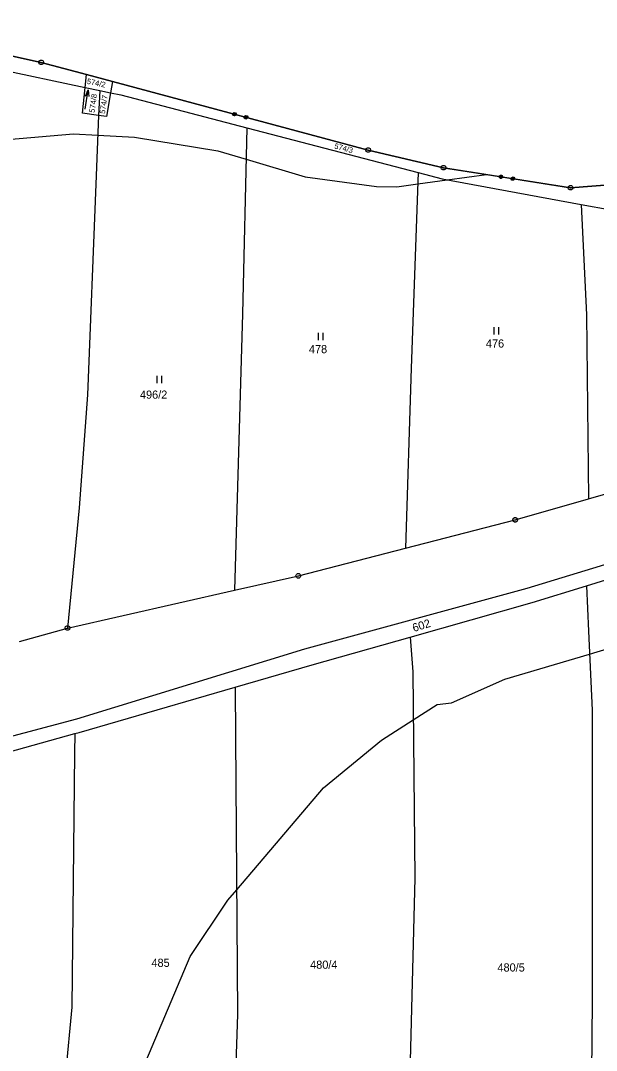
# Model space of a CAD drawing. Extents: x -760978 to -760029, y -1177282 to -1176414.
# Drawn here: x -760280.9 to -760161.1, y -1176642.6 to -1176428.3 of the extents above; entities that cross this region are included whole.
import ezdxf

# ---------------------------------------------------------------- set-up
doc = ezdxf.new("R2010")
doc.units = 0
for name, color, linetype in [('1', 7, 'Continuous'), ('11', 7, 'Continuous'), ('2', 7, 'Continuous'), ('3', 7, 'Continuous'), ('8', 7, 'Continuous')]:
    doc.layers.add(name, color=color, linetype=linetype)

msp = doc.modelspace()

# ---------------------------------------------------------------- linework, layer by layer
at = {"layer": '1'}
for p, q in [((-760276.6, -1176437.03), (-760316.13, -1176428.34)), ((-760296.58, -1176436.11), (-760267.45, -1176442.25)), ((-760267.18, -1176439.56), (-760276.6, -1176437.03)), ((-760267.45, -1176442.25), (-760267.18, -1176439.56)), ((-760261.76, -1176441.01), (-760267.18, -1176439.56)), ((-760261.76, -1176441.01), (-760262.18, -1176443.36)), ((-760208.55, -1176455.27), (-760261.76, -1176441.01)), ((-760267.99, -1176447.61), (-760267.45, -1176442.25)), ((-760267.45, -1176442.25), (-760264.44, -1176442.88)), ((-760264.44, -1176442.88), (-760264.66, -1176448.07)), ((-760264.44, -1176442.88), (-760262.18, -1176443.36)), ((-760262.18, -1176443.36), (-760263.05, -1176448.29)), ((-760262.18, -1176443.36), (-760260.03, -1176443.81)), ((-760260.03, -1176443.81), (-760233.79, -1176450.66)), ((-760264.66, -1176448.07), (-760267.99, -1176447.61)), ((-760264.66, -1176448.07), (-760265.25, -1176462.4)), ((-760263.05, -1176448.29), (-760264.66, -1176448.07)), ((-760233.79, -1176450.66), (-760234.75, -1176489.37)), ((-760233.79, -1176450.66), (-760198.18, -1176459.96)), ((-760192.88, -1176458.96), (-760208.55, -1176455.27)), ((-760198.18, -1176459.96), (-760199.63, -1176500.65)), ((-760198.18, -1176459.96), (-760193.14, -1176461.28)), ((-760166.44, -1176463.13), (-760192.88, -1176458.96)), ((-760265.25, -1176462.4), (-760266.96, -1176506.18)), ((-760193.14, -1176461.28), (-760164.28, -1176466.59)), ((-760157.62, -1176462.47), (-760166.44, -1176463.13)), ((-760164.28, -1176466.59), (-760163.15, -1176489.6)), ((-760164.28, -1176466.59), (-760158.05, -1176467.74)), ((-760234.75, -1176489.37), (-760236.35, -1176546.88)), ((-760163.15, -1176489.6), (-760162.74, -1176527.85)), ((-760199.63, -1176500.65), (-760200.78, -1176538.13)), ((-760266.96, -1176506.18), (-760268.68, -1176529.73)), ((-760162.74, -1176527.85), (-760149.74, -1176524.1)), ((-760177.97, -1176532.25), (-760162.74, -1176527.85)), ((-760268.68, -1176529.73), (-760271.14, -1176554.74)), ((-760125.87, -1176531.35), (-760175.55, -1176546.51)), ((-760200.78, -1176538.13), (-760177.97, -1176532.25)), ((-760223.1, -1176543.89), (-760200.78, -1176538.13)), ((-760163.15, -1176545.96), (-760149.68, -1176541.8)), ((-760236.35, -1176546.88), (-760223.1, -1176543.89)), ((-760174.45, -1176549.45), (-760163.15, -1176545.96)), ((-760163.15, -1176545.96), (-760162.73, -1176555.41)), ((-760271.14, -1176554.74), (-760236.35, -1176546.88)), ((-760175.55, -1176546.51), (-760221.79, -1176559.17)), ((-760199.81, -1176556.62), (-760174.45, -1176549.45)), ((-760281.11, -1176557.51), (-760271.14, -1176554.74)), ((-760220.2, -1176562.38), (-760199.81, -1176556.62)), ((-760199.81, -1176556.62), (-760199.29, -1176563.86)), ((-760162.73, -1176555.41), (-760161.99, -1176571.84)), ((-760221.79, -1176559.17), (-760269.28, -1176573.68)), ((-760236.24, -1176567.03), (-760220.2, -1176562.38)), ((-760199.29, -1176563.86), (-760198.83, -1176606.8)), ((-760268.74, -1176576.46), (-760236.24, -1176567.03)), ((-760236.24, -1176567.03), (-760236.16, -1176577.36)), ((-760161.99, -1176571.84), (-760161.99, -1176632.33)), ((-760269.28, -1176573.68), (-760302.72, -1176582.55)), ((-760285.28, -1176581.08), (-760269.62, -1176576.7)), ((-760269.62, -1176576.7), (-760269.67, -1176580.75)), ((-760269.62, -1176576.7), (-760268.74, -1176576.46)), ((-760236.16, -1176577.36), (-760235.73, -1176635.17)), ((-760269.67, -1176580.75), (-760270.26, -1176633.65)), ((-760198.83, -1176606.8), (-760200.41, -1176667.45)), ((-760270.26, -1176633.65), (-760272.99, -1176662.87)), ((-760161.99, -1176632.33), (-760162.36, -1176686.44)), ((-760235.73, -1176635.17), (-760237.83, -1176693.67))]:
    msp.add_line(p, q, dxfattribs=at)
for points in [[(-760236.62, -1176448.08), (-760236.75, -1176447.85), (-760236.68, -1176447.59), (-760236.45, -1176447.45), (-760236.19, -1176447.52), (-760236.06, -1176447.75), (-760236.13, -1176448.01), (-760236.36, -1176448.15), (-760236.62, -1176448.08), (-760236.58, -1176448.05), (-760236.35, -1176448.11), (-760236.25, -1176448.05), (-760236.64, -1176447.95), (-760236.69, -1176447.85), (-760236.15, -1176448), (-760236.13, -1176447.92), (-760236.67, -1176447.78), (-760236.65, -1176447.7), (-760236.11, -1176447.84), (-760236.09, -1176447.77), (-760236.63, -1176447.62), (-760236.53, -1176447.56), (-760236.15, -1176447.67), (-760236.2, -1176447.57), (-760236.43, -1176447.51)], [(-760234.2, -1176448.73), (-760234.34, -1176448.49), (-760234.27, -1176448.23), (-760234.04, -1176448.1), (-760233.78, -1176448.17), (-760233.64, -1176448.4), (-760233.71, -1176448.66), (-760233.94, -1176448.8), (-760234.2, -1176448.73), (-760234.18, -1176448.69), (-760233.95, -1176448.75), (-760233.85, -1176448.7), (-760234.24, -1176448.59), (-760234.3, -1176448.49), (-760233.76, -1176448.64), (-760233.74, -1176448.56), (-760234.28, -1176448.42), (-760234.26, -1176448.34), (-760233.72, -1176448.48), (-760233.69, -1176448.41), (-760234.24, -1176448.26), (-760234.14, -1176448.21), (-760233.75, -1176448.31), (-760233.81, -1176448.21), (-760234.04, -1176448.15)], [(-760181.12, -1176461.14), (-760181.28, -1176460.92), (-760181.24, -1176460.65), (-760181.02, -1176460.5), (-760180.75, -1176460.54), (-760180.6, -1176460.76), (-760180.64, -1176461.02), (-760180.86, -1176461.18), (-760181.12, -1176461.14), (-760181.09, -1176461.1), (-760180.85, -1176461.14), (-760180.76, -1176461.07), (-760181.15, -1176461.01), (-760181.22, -1176460.92), (-760180.67, -1176461.01), (-760180.65, -1176460.93), (-760181.21, -1176460.84), (-760181.19, -1176460.76), (-760180.64, -1176460.85), (-760180.63, -1176460.77), (-760181.18, -1176460.68), (-760181.09, -1176460.62), (-760180.7, -1176460.68), (-760180.76, -1176460.59), (-760181, -1176460.55)], [(-760178.65, -1176461.53), (-760178.81, -1176461.31), (-760178.77, -1176461.04), (-760178.55, -1176460.89), (-760178.28, -1176460.93), (-760178.13, -1176461.15), (-760178.17, -1176461.41), (-760178.39, -1176461.57), (-760178.65, -1176461.53), (-760178.64, -1176461.49), (-760178.4, -1176461.53), (-760178.31, -1176461.46), (-760178.7, -1176461.4), (-760178.77, -1176461.31), (-760178.22, -1176461.39), (-760178.2, -1176461.32), (-760178.76, -1176461.23), (-760178.75, -1176461.15), (-760178.19, -1176461.24), (-760178.18, -1176461.16), (-760178.73, -1176461.07), (-760178.64, -1176461), (-760178.25, -1176461.07), (-760178.31, -1176460.97), (-760178.55, -1176460.94)]]:
    msp.add_lwpolyline(points, dxfattribs=at)
at = {"layer": '11'}
for points in [[(-760610.45, -1176430.21), (-760611.11, -1176435.21), (-760607.21, -1176435.9), (-760556.03, -1176460.82), (-760555.89, -1176460.89), (-760545.74, -1176465.83), (-760487.96, -1176478.86), (-760457.63, -1176475.7), (-760439.57, -1176472.8), (-760424.85, -1176466.78), (-760424.82, -1176466.77), (-760413.52, -1176462.15), (-760377.01, -1176441.98), (-760344.63, -1176429.59), (-760316.13, -1176428.34), (-760276.6, -1176437.03), (-760267.18, -1176439.56), (-760261.76, -1176441.01)], [(-760261.76, -1176441.01), (-760208.55, -1176455.27), (-760192.88, -1176458.96), (-760183.97, -1176460.36)], [(-760183.97, -1176460.36), (-760166.44, -1176463.13), (-760157.62, -1176462.47), (-760153.69, -1176462.18), (-760135.67, -1176460.84), (-760121.19, -1176458.87), (-760106.95, -1176454.96), (-760087.58, -1176448.84)], [(-760463.52, -1176510.97), (-760456.38, -1176508.74), (-760455.84, -1176508.57), (-760440.39, -1176497.85), (-760434.43, -1176496.69), (-760400.64, -1176484.31), (-760369.55, -1176472.91), (-760361.85, -1176469.24), (-760336.22, -1176462.2), (-760324.34, -1176458.93), (-760306.03, -1176455.04), (-760299.86, -1176454.5), (-760269.91, -1176451.9), (-760264.83, -1176452.17), (-760257.19, -1176452.57), (-760239.84, -1176455.43), (-760233.95, -1176457.19), (-760221.69, -1176460.86), (-760206.87, -1176462.83), (-760202.63, -1176462.91), (-760198.26, -1176462.31), (-760192.1, -1176461.47), (-760183.97, -1176460.36)], [(-760254.86, -1176644.92), (-760245.59, -1176623.07), (-760237.75, -1176611.35), (-760235.92, -1176609.2), (-760217.85, -1176588), (-760205.81, -1176578.07), (-760199.18, -1176573.83), (-760194.23, -1176570.66), (-760191.25, -1176570.29), (-760180.14, -1176565.41), (-760162.52, -1176560.15), (-760149.44, -1176556.25), (-760149.34, -1176556.23), (-760124.36, -1176551.99), (-760117.95, -1176550.9), (-760100.57, -1176548.71), (-760087.11, -1176547.01), (-760071.18, -1176545), (-760059.84, -1176544.57), (-760056.32, -1176544.43)]]:
    msp.add_lwpolyline(points, dxfattribs=at)
at = {"layer": '3'}
for p, q in [((-760267.45, -1176446.74), (-760266.83, -1176442.76)), ((-760182.4, -1176492.16), (-760182.4, -1176493.66)), ((-760181.4, -1176493.66), (-760181.4, -1176492.16)), ((-760218.96, -1176493.32), (-760218.96, -1176494.82)), ((-760217.96, -1176494.82), (-760217.96, -1176493.32)), ((-760252.53, -1176502.27), (-760252.53, -1176503.77)), ((-760251.53, -1176503.77), (-760251.53, -1176502.27))]:
    msp.add_line(p, q, dxfattribs=at)
msp.add_lwpolyline([(-760267.37, -1176444.04), (-760266.83, -1176442.76), (-760266.7, -1176444.14)], dxfattribs=at)
at = {"layer": '8'}
for p, q in [((-760276.72, -1176437.03), (-760276.48, -1176437.03)), ((-760208.67, -1176455.27), (-760208.43, -1176455.27)), ((-760193, -1176458.96), (-760192.76, -1176458.96)), ((-760166.56, -1176463.13), (-760166.32, -1176463.13)), ((-760178.09, -1176532.25), (-760177.85, -1176532.25)), ((-760223.22, -1176543.89), (-760222.98, -1176543.89)), ((-760271.26, -1176554.74), (-760271.02, -1176554.74))]:
    msp.add_line(p, q, dxfattribs=at)
for points in [[(-760276.45, -1176436.55), (-760276.2, -1176436.73), (-760276.1, -1176437.02), (-760276.2, -1176437.31), (-760276.45, -1176437.49), (-760276.76, -1176437.49), (-760277.01, -1176437.31), (-760277.11, -1176437.02), (-760277.01, -1176436.73), (-760276.76, -1176436.55)], [(-760208.4, -1176454.79), (-760208.15, -1176454.97), (-760208.05, -1176455.26), (-760208.15, -1176455.55), (-760208.4, -1176455.73), (-760208.71, -1176455.73), (-760208.96, -1176455.55), (-760209.06, -1176455.26), (-760208.96, -1176454.97), (-760208.71, -1176454.79)], [(-760192.73, -1176458.48), (-760192.48, -1176458.66), (-760192.38, -1176458.95), (-760192.48, -1176459.24), (-760192.73, -1176459.42), (-760193.04, -1176459.42), (-760193.29, -1176459.24), (-760193.39, -1176458.95), (-760193.29, -1176458.66), (-760193.04, -1176458.48)], [(-760166.29, -1176462.65), (-760166.04, -1176462.83), (-760165.94, -1176463.12), (-760166.04, -1176463.41), (-760166.29, -1176463.59), (-760166.6, -1176463.59), (-760166.85, -1176463.41), (-760166.95, -1176463.12), (-760166.85, -1176462.83), (-760166.6, -1176462.65)], [(-760177.82, -1176531.77), (-760177.57, -1176531.95), (-760177.47, -1176532.24), (-760177.57, -1176532.53), (-760177.82, -1176532.71), (-760178.13, -1176532.71), (-760178.38, -1176532.53), (-760178.48, -1176532.24), (-760178.38, -1176531.95), (-760178.13, -1176531.77)], [(-760222.95, -1176543.41), (-760222.7, -1176543.59), (-760222.6, -1176543.88), (-760222.7, -1176544.17), (-760222.95, -1176544.35), (-760223.26, -1176544.35), (-760223.51, -1176544.17), (-760223.61, -1176543.88), (-760223.51, -1176543.59), (-760223.26, -1176543.41)], [(-760270.99, -1176554.26), (-760270.74, -1176554.44), (-760270.64, -1176554.73), (-760270.74, -1176555.02), (-760270.99, -1176555.2), (-760271.3, -1176555.2), (-760271.55, -1176555.02), (-760271.65, -1176554.73), (-760271.55, -1176554.44), (-760271.3, -1176554.26)]]:
    msp.add_lwpolyline(points, close=True, dxfattribs=at)

# ---------------------------------------------------------------- texts
at = {"layer": '2'}
for s, height, rotation, p in [('574/2', 1.14, 347.9, (-760267.2, -1176441.47)), ('574/8', 1.14, 82.4486, (-760265.51, -1176447.58)), ('574/7', 1.14, 80.787, (-760263.37, -1176447.82)), ('574/3', 1.14, 345.0925, (-760215.7, -1176454.93)), ('602', 1.7, 17.246, (-760199.06, -1176555.57))]:
    msp.add_text(s, height=height, rotation=rotation, dxfattribs=at).set_placement(p)
for s, p in [('476', (-760184.07, -1176496.38)), ('478', (-760220.9, -1176497.55)), ('496/2', (-760256.06, -1176507.02)), ('485', (-760253.67, -1176625.25)), ('480/4', (-760220.65, -1176625.64)), ('480/5', (-760181.67, -1176626.22))]:
    msp.add_text(s, height=1.7, dxfattribs=at).set_placement(p)

doc.saveas('drawing.dxf')
